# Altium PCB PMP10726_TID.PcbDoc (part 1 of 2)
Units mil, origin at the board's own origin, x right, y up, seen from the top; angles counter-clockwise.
Board outline 1200 x 2800 mil, 4 copper layers (Top Layer, Inner Layer 1, Inner Layer 2, Bottom Layer), stack 60.2 mil thick; 86 components, 43 nets, 209 pads, 170 vias.
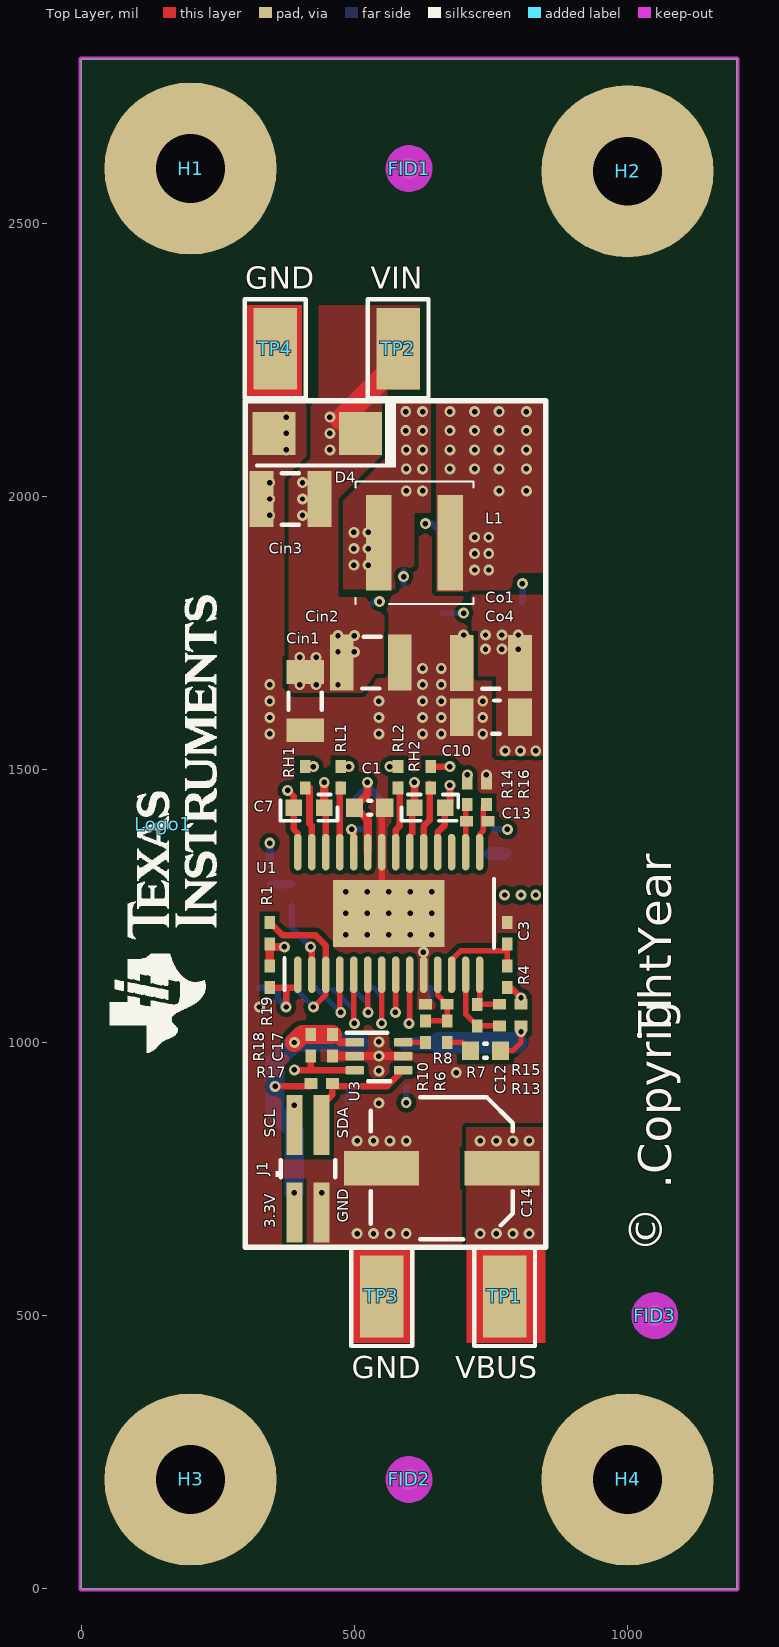
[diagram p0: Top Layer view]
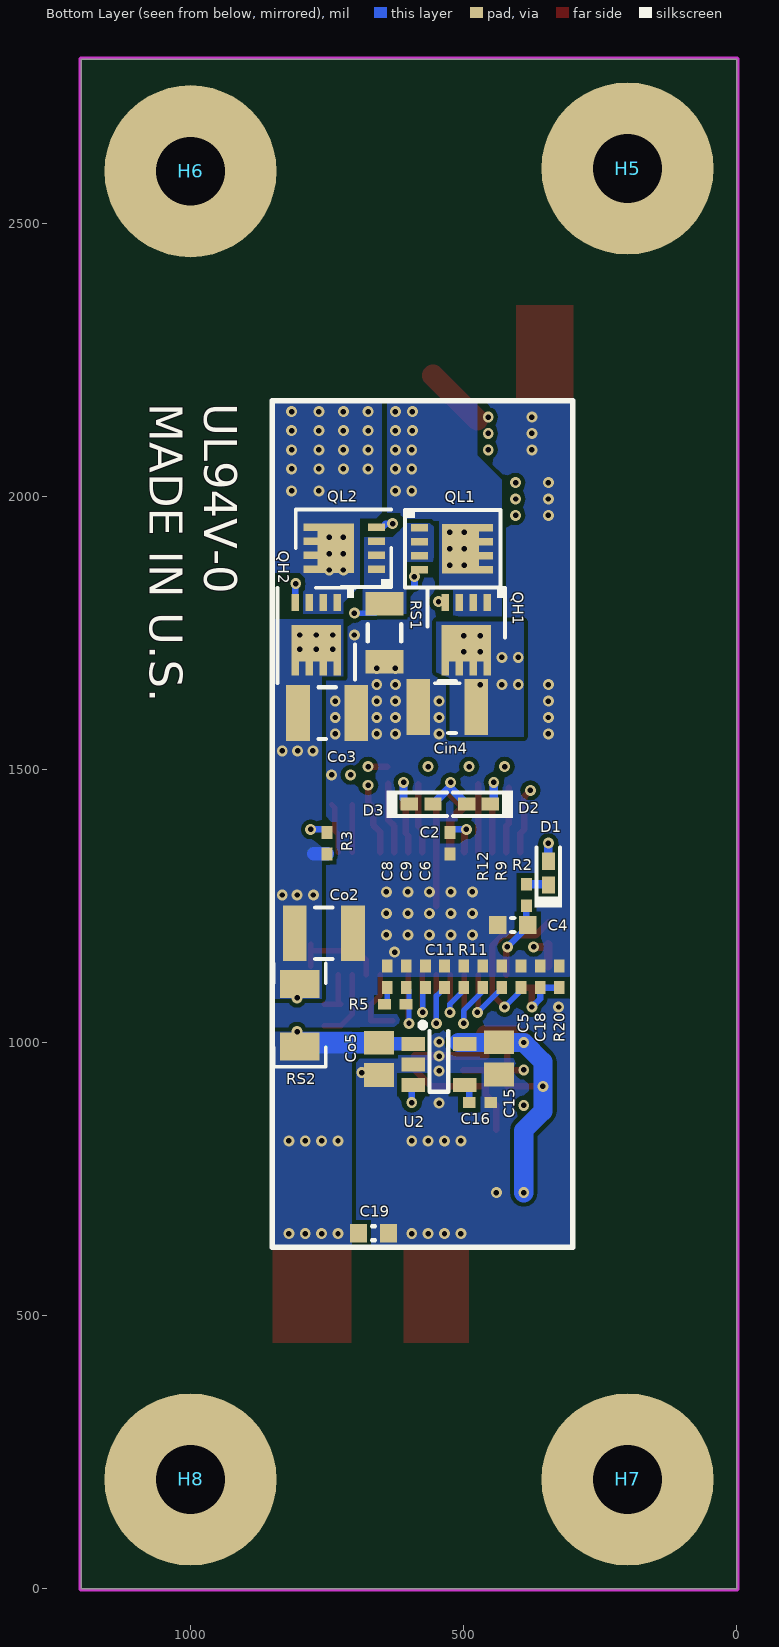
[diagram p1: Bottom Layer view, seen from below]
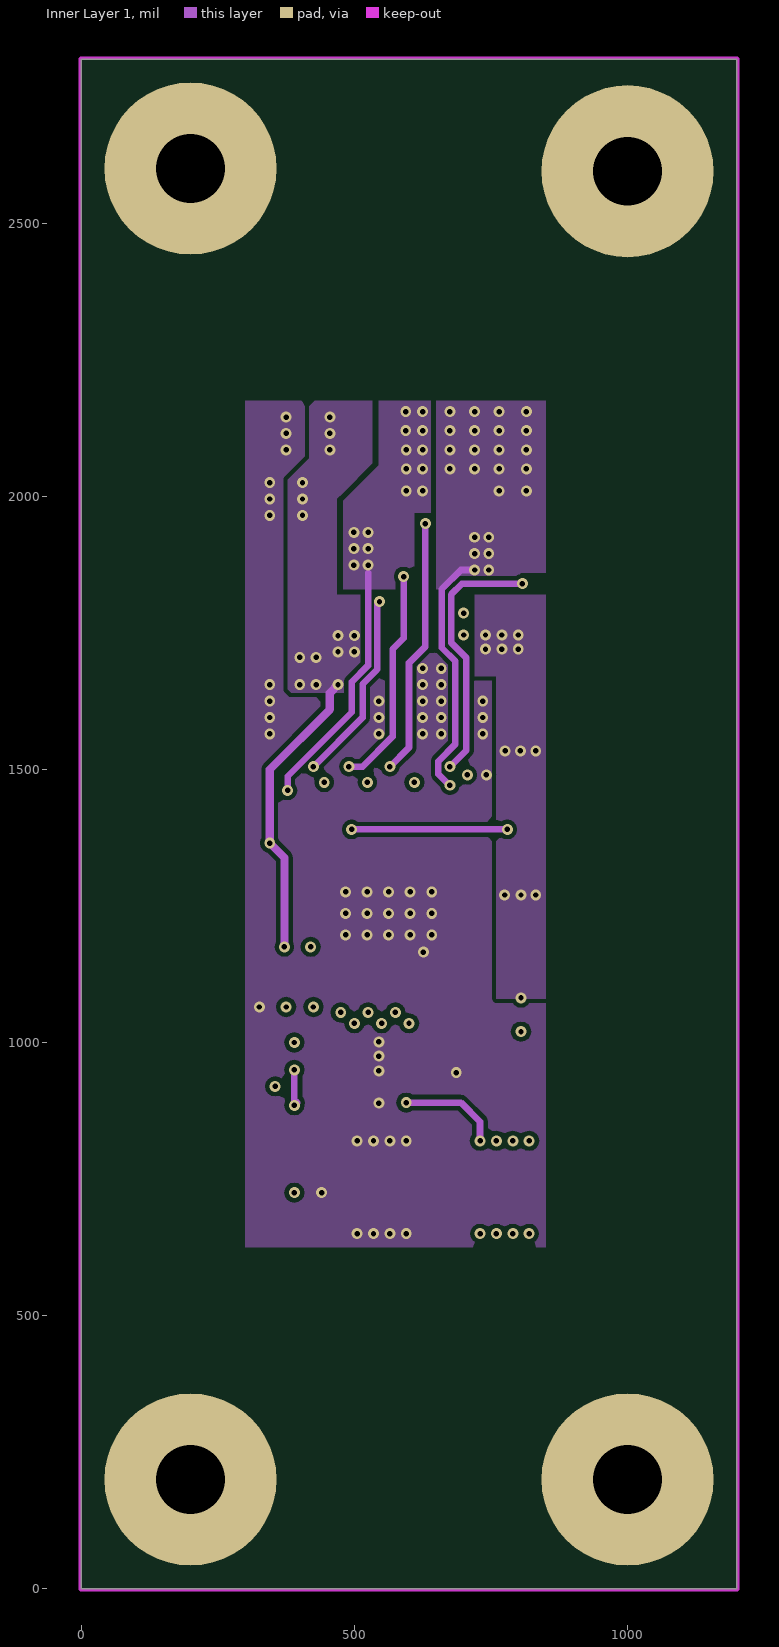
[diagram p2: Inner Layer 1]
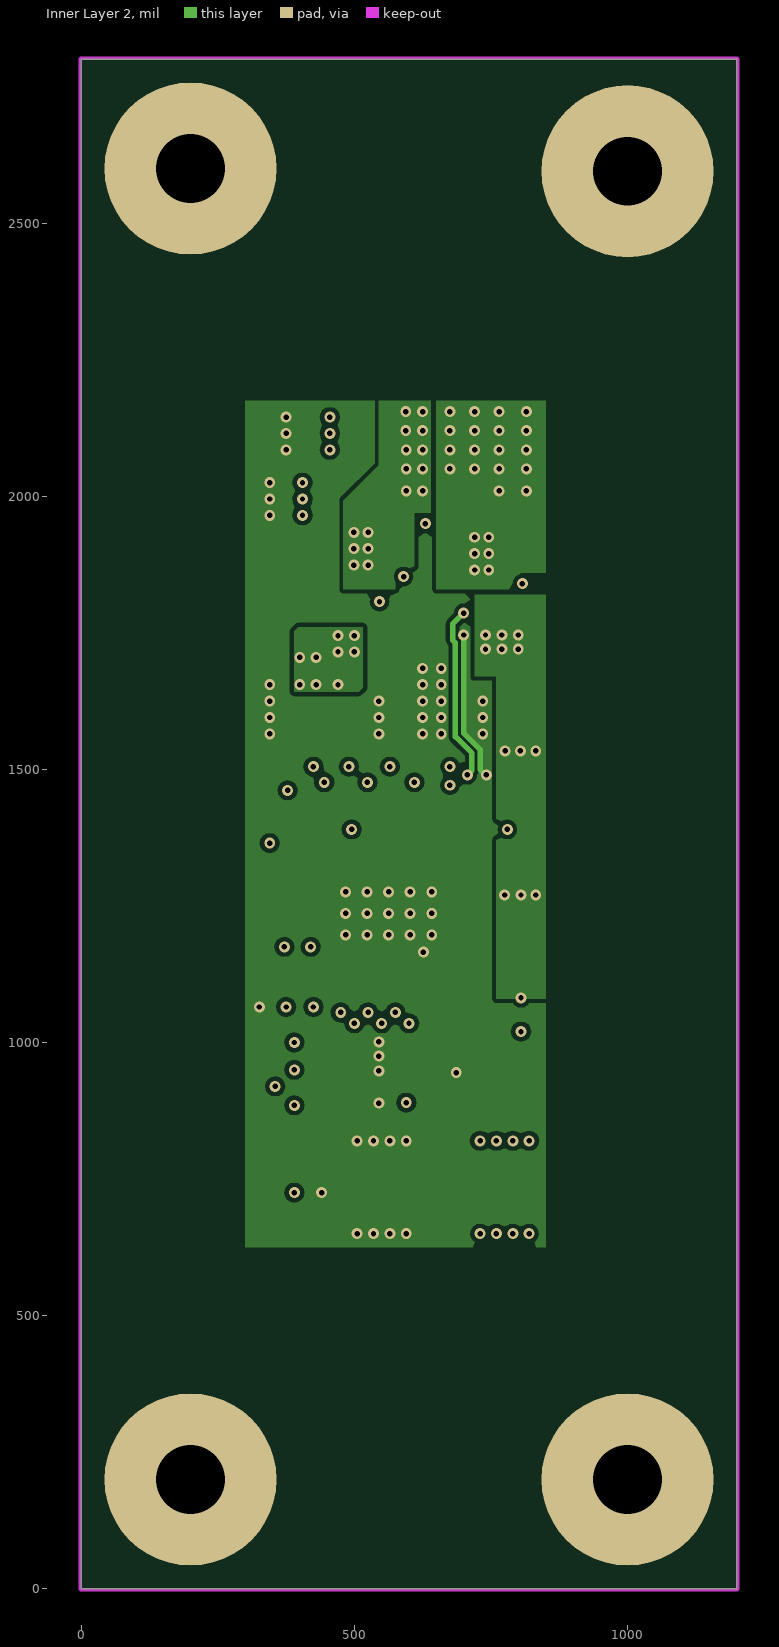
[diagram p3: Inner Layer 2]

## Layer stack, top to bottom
Top Solder: solder mask 0.5, Solder Resist, Dk 3.5
Top Layer: signal copper 2.8
Dielectric 1: prepreg 9.1, FR-4, Dk 4.2
Inner Layer 1: signal copper 2.8
Dielectric 2: core 30.8, FR-4, Dk 4.2
Inner Layer 2: signal copper 2.8
Dielectric 3: prepreg 9.1, FR-4, Dk 4.2
Bottom Layer: signal copper 2.8
Bottom Solder: solder mask 0.5, Solder Resist, Dk 3.5

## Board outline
0,0 1200,0 1200,2800 0,2800

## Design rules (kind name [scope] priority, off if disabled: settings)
AcuteAngle [All] p1: minimum=4.50000000000000E+0001 checktracksonly=FALSE
AssemblyTestPointUsage [All] p1: valid=2
Clearance "Clearance_POLY to NPTH" [HasFootprint('CONN_JPD1135-509') vs InPolygon] p1: gap=10
Clearance Clearance_Keepouts [((IsTrack Or IsArc) And Not InPoly) And IsFree and IsKeepOut vs ((IsTrack Or IsArc) And Not InPoly) And IsFree and IsKeepOut] p2: gap=0
Clearance Clearance_BoardEdge_MountingHoles [OnCopper and InComponentClass('Mounting Holes') vs IsKeepOut] p3: gap=40
Clearance Clearance_BoardEdge_Poly [OnCopper and InPoly vs IsKeepOut] p4: gap=25
Clearance Clearance_BoardEdge [OnCopper and Not InComponentClass('Logo') and not InComponentClass('FiducialMark') and not InRegion(1000,500,4000,800) and Not IsKeepout vs IsKeepOut] p5: gap=20
Clearance Clearance_Poly [InPolygon] p6: gap=8
Clearance [All] p7: gap=5
ComponentClearance ComponentClearance_MountingHoles_FiducialMarks [InComponentClass('Mounting Holes') vs InComponentClass('FiducialMark')] p1: gap=20 collisioncheckmode=3 verticalgap=10 showdistances=FALSE
ComponentClearance ComponentClearance_Shunt [InComponentClass('Header') vs InComponentClass('Shunt')] p2: gap=0 collisioncheckmode=3 verticalgap=0 showdistances=FALSE
ComponentClearance ComponentClearance_Logo [InComponentClass('Logo')] p3: gap=50 collisioncheckmode=3 verticalgap=10 showdistances=FALSE
ComponentClearance ComponentClearance_ScrewToNut [(HasFootprint('NY PMS 440 0025 PH')) vs (HasFootprint('Keystone_1902C'))] p4: gap=5 collisioncheckmode=3 verticalgap=10 showdistances=FALSE
ComponentClearance ComponentClearance_MountingHoles [InComponentClass('Mounting Holes')] p5: gap=50 collisioncheckmode=3 verticalgap=100000 showdistances=FALSE
ComponentClearance ComponentClearance_SmallPassives [HasFootprint('0201*') or HasFootprint('0402*') or HasFootprint('0508') or HasFootprint('0603*') or HasFootprint('0612') or HasFootprint('0805*') or HasFootprint('0815*') or HasFootprint('0830*') or HasFootprint('1206*') or HasFootprint('1210*') or HasFootprint('1808*') or HasFootprint('1812*') or HasFootprint('1825*') or HasFootprint('2010*') or HasFootprint('2220*') or HasFootprint('2225*') or HasFootprint('2512*') or HasFootprint('2728*') or HasFootprint('3518*') vs HasFootprint('0201*') or HasFootprint('0402*') or HasFootprint('0508') or HasFootprint('0603*') or HasFootprint('0612') or HasFootprint('0805*') or HasFootprint('0815*') or HasFootprint('0830*') or HasFootprint('1206*') or HasFootprint('1210*') or HasFootprint('1808*') or HasFootprint('1812*') or HasFootprint('1825*') or HasFootprint('2010*') or HasFootprint('2220*') or HasFootprint('2225*') or HasFootprint('2512*') or HasFootprint('2728*') or HasFootprint('3518*')] p6: gap=10 collisioncheckmode=3 verticalgap=10 showdistances=FALSE
ComponentClearance ComponentClearance_THtoSMT [IsThruComponent vs IsSMTComponent] p7: gap=20 collisioncheckmode=3 verticalgap=30 showdistances=FALSE
ComponentClearance ComponentClearance_THtoTH [IsThruComponent vs IsThruComponent] p8: gap=50 collisioncheckmode=3 verticalgap=30 showdistances=FALSE
ComponentClearance [All] p9: gap=9.9 collisioncheckmode=3 verticalgap=10 showdistances=FALSE
DiffPairsRouting [All] p1: maxlimit=100 minlimit=6 mostfreqgap=6 toplayer_minwidth=4 toplayer_maxwidth=15 toplayer_prefwidth=5 midlayer1_minwidth=4 midlayer1_maxwidth=15 midlayer1_prefwidth=5 midlayer2_minwidth=4 midlayer2_maxwidth=15 midlayer2_prefwidth=5 bottomlayer_minwidth=4 bottomlayer_maxwidth=15 bottomlayer_prefwidth=5 maxuncoupledlength=1000
FabricationTestPointUsage TestPointUsage [All] p1: valid=2 allowmultiple=FALSE
FabricationTestpoint Testpoint [All] p1: side=3 testpointundercomponent=TRUE minsize=40 maxsize=100 preferedsize=60 minholesize=0 maxholesize=40 preferedholesize=32 testpointgrid=1 allowsidetop=TRUE allowsidebottom=TRUE usegrid=TRUE gridtolerance=0.01
FanoutControl Fanout_LCC [IsLCC] p1: bgadir=Out bgaviamode=Centered fanoutstyle=Auto fanoutdirection=Alternating viagrid=1 // Fanout_LCC (Default Rule)
FanoutControl Fanout_BGA [IsBGA] p2: bgadir=Out bgaviamode=Centered fanoutstyle=Auto fanoutdirection=Alternating viagrid=1 // Fanout_BGA (Default Rule)
FanoutControl Fanout_Default [All] p4: bgadir=Out bgaviamode=Centered fanoutstyle=Auto fanoutdirection=Alternating viagrid=1 // Fanout_Default (Default Rule)
FanoutControl Fanout_Small [(CompPinCount < 5)] p5: bgadir=Out bgaviamode=Centered fanoutstyle=Auto fanoutdirection=OutThenIn viagrid=1 // Fanout_Small (Default Rule)
HoleSize [All] p1: absolutevalues=TRUE maxlimit=251 minlimit=10 maxpercent=80.000 minpercent=20.000
HoleToHoleClearance "HoleToHoleClearance_USB-C Connector" [HasFootprint('Lintes_20-0000016-01') vs HasFootprint('Lintes_20-0000016-01')] p1: gap=0 allowstackedmicrovias=TRUE
HoleToHoleClearance [All] p2: gap=10 allowstackedmicrovias=TRUE
MinimumAnnularRing MinimumAnnularRing_ThermalPadVias [IsVia and InAnyComponent] p1: minimumring=5
MinimumAnnularRing [All] p2: minimumring=5
MinimumSolderMaskSliver "MinimumSolderMaskSliver_USB-C Connector" [HasFootprint('Lintes_20-0000016-01')] p1: minsoldermaskwidth=3.6
MinimumSolderMaskSliver MinimumSolderMaskSliver_FemtoFET [HasFootprint('YJC0003A') vs HasFootprint('YJC0003A')] p2: minsoldermaskwidth=3.54
MinimumSolderMaskSliver MinimumSolderMaskSliver_LM53600 [HasFootprint('DSX0010A') vs HasFootprint('DSX0010A')] p3: minsoldermaskwidth=0
MinimumSolderMaskSliver MinimumSolderMaskSliver_TPS65982 [HasFootprint('ZQZ0096A_Oval')] p4: minsoldermaskwidth=3.6
MinimumSolderMaskSliver MinimumSolderMaskSliver_Logo [InComponentClass('Logo') vs InComponentClass('Logo')] p5: minsoldermaskwidth=0.7
MinimumSolderMaskSliver [All] p6: minsoldermaskwidth=2
ParallelSegment [All] p1: limit=500 gap=4
PlaneClearance [All] p1: clearance=10
PlaneConnect [All] p1: planeconnectstyle=Direct reliefexpansion=10 reliefentries=4 reliefconductorwidth=10 reliefairgap=10
PolygonConnect [All] p1: connectstyle=Direct reliefconductorwidth=10 reliefentries=4 polygonreliefangle="90 Angle" airgapwidth=10
RoutingVias ThermalPadVias [IsVia and InAnyComponent] p1: holewidth=7.87 width=19.68 viastyle="Through Hole" minholewidth=7.87 minwidth=16 maxholewidth=12.99 maxwidth=23.62
RoutingVias [All] p2: holewidth=16 width=34 viastyle="Through Hole" minholewidth=7.87 minwidth=16 maxholewidth=40 maxwidth=65
SilkToBoardRegionClearance [Not ((IsComment or IsDesignator) And (Hide <> 'False')) and not InRegion(1000,500,4000,800)] p1:
SilkToSilkClearance SilkToSilkClearance_Pb-FreeLogo [(HasFootprint('Pb-Free_Overlay_Medium') OR HasFootprint('Pb-Free_Overlay_Small')) vs (HasFootprint('Pb-Free_Overlay_Medium') OR HasFootprint('Pb-Free_Overlay_Small'))] p1: silktosilkclearance=0
SilkToSilkClearance [All] p2: silktosilkclearance=3
SilkToSolderMaskClearance "Silk to Solder Mask Opening" [All] p1: minsilkscreentomaskgap=1 clearancetoexposedcopper=FALSE
SolderMaskExpansion [All] p1: expansion=1.97
Width [All] p1: maxlimit=100 minlimit=5 preferedwidth=8
13 further rules are at their usual default settings.

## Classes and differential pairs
component class PMP10726B_Power: C1 C2 C3 C4 C5 C6 C7 C8 C9 C10 C11 C12 C13 C14 C15 C16 C17 C18 C19 C? Cin1 Cin2 Cin3 Cin4 Co1 Co2 Co3 Co4 Co5 D1 D2 D3 D4 L1 QH1 QH2 QL1 QL2 R1 R2 R3 R4 R5 R6 R7 R8 R9 R10 R11 R12 R13 R14 R15 R16 R17 R18 R19 R20 RH1 RH2 RL1 RL2 RS1 RS2 TP1 TP2 TP3 TP4 U1 U2 U3
component class AssemblyNote: ZZ1 ZZ2 ZZ3
component class FiducialMark: FID1 FID2 FID3
component class PMP10726B_Misc: FID1 FID2 FID3 H1 H2 H3 H4 H5 H6 H7 H8 Logo1 ZZ1 ZZ2 ZZ3
component class Logo: Logo1
component class "Mounting Holes": H1 H2 H3 H4

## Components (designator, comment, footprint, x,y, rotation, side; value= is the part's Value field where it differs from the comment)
C1 "GRM188R71E105KA12D" 0603l 528,1430 r0 top
C2 "C1005X7R1C224K050BC" 0402L 525,1365 r90 bottom
C3 "GRM1535C1H101JDD5D" 0402L 780,1200 r270 top
C4 "C1608X7R1H224K080AB" 0603L 410,1215 r180 bottom
C5 "GRM1535C1H101JDD5D" 0402L 395,1120 r270 bottom
C6 "C1005X7R1H473K050BB" 0402L 570,1120 r270 bottom
C7 "GCM188R71H104KA57D" 0603_HV 417,1430 r180 top
C8 "GCM155R71H223KA55D" 0402l 640,1120 r270 bottom
C9 "GRM1555C1H221JA01D" 0402l 605,1120 r270 bottom
C10 "GCM188R71H104KA57D" 0603_HV 638,1430 r0 top
C11 "GRM1555C1H680JA01D" 0402l 535,1120 r90 bottom
C12 "GRM1535C1H101JDD5D" 0402l 725,1050 r90 top
C13 "GRM1555C1H221JA01D" 0402l 725,1405 r0 top
C14 "UUD1C101MCL1GS" SM_RADIAL_6.3AMM 660,770 r180 top
C15 "GRM21BR71C475KA73L" 0805L 435,971 r90 bottom
C16 "GCM155R71H103KA55D" 0402L 470,890 r0 bottom
C17 "C1005X7R1C224K050BC" 0402L 460,995 r90 top
C18 "GRM1535C1H101JDD5D" 0402L 359.94,1120 r90 bottom
C19 "GRM188R71E105KA12D" 0603L 665,651 r0 bottom
Cin1 "GRM31CR71H475KA12L" 1206L 410,1625 r270 top
Cin2 "GRM32ER71H106KA12L" 1210L 530,1695.31 r0 top
Cin3 "GRM32ER71H106KA12L" 1210L 383,1995 r180 top
Cin4 "GRM32ER71H106KA12L" 1210L 530,1614 r0 bottom
Co1 "GRM32ER71E226KE15L" 1210L 750,1695 r180 top
Co2 "GRM32ER71E226KE15L" 1210L 755.73,1200 r180 bottom
Co3 "GRM32ER71E226KE15L" 1210L 750,1603 r180 bottom
Co4 "C3216X7R1E106M160AE" 1206L 750,1595.31 r180 top
Co5 "EMK212BB7106MG-T" 0805L 655,970 r270 bottom
D1 "BAS 52-02V H6327" SOD-523 345,1310 r90 bottom
D2 "BAS516,115" SOD-523 472.82,1436.3 r0 bottom
D3 "BAS516,115" SOD-523 577.82,1436.3 r180 bottom
D4 "SMAJ30CA" SMA 432,2115 r180 top
FID1 "Fiducial" Fiducial10-20 600,2600 r0 top
FID2 "Fiducial" Fiducial10-20 600,200 r0 top
FID3 "Fiducial" Fiducial10-20 1050,500 r0 top
H1 "NY PMS 440 0025 PH" "NY PMS 440 0025 PH" 200,2600 r0 top locked
H2 "NY PMS 440 0025 PH" "NY PMS 440 0025 PH" 1000,2595 r0 top locked
H3 "NY PMS 440 0025 PH" "NY PMS 440 0025 PH" 200,200 r0 top locked
H4 "NY PMS 440 0025 PH" "NY PMS 440 0025 PH" 1000,200 r0 top locked
H5 "1902C" Keystone_1902C 200,2600 r180 bottom locked
H6 "1902C" Keystone_1902C 1000,2595 r180 bottom locked
H7 "1902C" Keystone_1902C 200,200 r180 bottom locked
H8 "1902C" Keystone_1902C 1000,200 r180 bottom locked
J1 "FTSH-102-01-F-DV" Samtec_FTSH-102-01-x-DV 415,769 r90 top
L1 "XAL5050-562MEB" XAL5050 610,1915 r0 top
Logo1 "Texas Instruments" TI_Stacked_Overlay_Small 150,1400 r90 top
QH1 "BSZ025N04LSATMA1" PG-TSDSON-8 495,1745 r270 bottom
QH2 "BSZ025N04LSATMA1" PG-TSDSON-8 770,1745 r270 bottom
QL1 "BSZ025N04LSATMA1" PG-TSDSON-8 520,1904 r180 bottom
QL2 "BSZ025N04LSATMA1" PG-TSDSON-8 720,1905 r0 bottom
R1 "CRCW040210R0JNED" 0402l 345,1200 r270 top
R2 "CRCW040210R0JNED" 0402l 385,1270 r90 bottom
R3 "CRCW040210R0JNED" 0402l 750,1365 r270 bottom
R4 "CRCW040210R0JNED" 0402L 780,1120 r270 top
R5 "CRCW04023K32FKED" 0402l 625,1070 r180 bottom
R6 "CRCW040249K9FKED" 0402L 670,1020 r90 top
R7 "CRCW060324R9FKEA" 0603L 740,985 r0 top
R8 "CRCW0402115KFKED" 0402L 650,1070 r180 top
R9 "CRCW0402100KFKED" 0402l 430,1120 r90 bottom
R10 "CRCW04023K57FKED" 0402L 630,1020 r270 top
R11 "CRCW040264K9FKED" 0402l 500,1120 r90 bottom
R12 "CRCW04020000Z0ED" 0402l 465,1120 r90 bottom
R13 "CRCW04020000Z0ED" 0402L 785,1030 r180 top
R14 "CRCW0402100RFKED" 0402l 706.81,1455.35 r90 top
R15 "CRCW04020000Z0ED" 0402L 785,1070 r180 top
R16 "CRCW0402100RFKED" 0402l 741.81,1455.35 r90 top
R17 "CRCW04023K32FKED" 0402L 440,925 r180 top
R18 "CRCW04023K32FKED" 0402L 420,995 r90 top
R19 "CRCW0402200KFKED" 0402L 345,1120 r270 top
R20 "CRCW040249K9FKED" 0402L 324.94,1120 r90 bottom
RH1 "CRCW04020000Z0ED" 0402L 410,1485.35 r90 top
RH2 "CRCW04020000Z0ED" 0402L 640,1485.35 r270 top
RL1 "CRCW04020000Z0ED" 0402L 475,1485.35 r90 top
RL2 "CRCW04020000Z0ED" 0402L 580,1485.35 r270 top
RS1 "WSLP1206R0100FEA" 1206L 645,1750 r90 bottom
RS2 "WSLP1206R0100FEA" 1206 800,1050 r270 bottom
TP1 "VBUS" Keystone_5019 775,535 r90 top
TP2 "VIN" Keystone_5019 580,2270 r90 top
TP3 "GND" Keystone_5019 550,535 r270 top
TP4 "GND" Keystone_5019 355,2270 r90 top
U1 "LM5175PWPR" PWP0028F_N 562.82,1236.3 r90 top
U2 "LP2985AIM5-3.3/NOPB" MF05A_N 545,960 r180 bottom
U3 "TPL0401A-10DCKR" DCK0006A_N 545,975 r0 top
ZZ1 "These assemblies are ESD sensitive, ESD precautions shall be observed." AssemblyNote -11,3159 r0 top
ZZ2 "These assemblies must be clean and free from flux and all contaminants. Use of no clean flux is not acceptable." AssemblyNote -11,3079 r0 top
ZZ3 "These assemblies must comply with workmanship standards IPC-A-610 Class 2, unless otherwise specified." AssemblyNote -11,2999 r0 top

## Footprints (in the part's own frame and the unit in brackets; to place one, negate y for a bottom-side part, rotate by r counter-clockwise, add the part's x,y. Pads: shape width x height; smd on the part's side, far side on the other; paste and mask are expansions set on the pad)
0402L [mm] "0402 from SM-752 data"
  rect 0.6x0.5 smd: 1(-0.5,0) 2(0.5,0)
  body extent -0.55,-0.3 0.55,0.3, height 0.6
0402l [mm] "0402 from SM-752 data"
  rect 0.6x0.5 smd: 1(-0.5,0) 2(0.5,0)
  body extent -0.55,-0.3 0.55,0.3, height 0.6
0603_HV [mil] "Ernesto recommended land pattern.  26 mil between pads."
  rect 30x30 smd: 1(-28,0) 2(28,0)
  silkscreen extent -52,-24 52,24, body extent -34,-19 34,19, height 33
0603l [mm] "0603 from SM-752 data"
  rect 0.8x0.85 smd: 1(-0.7,0) 2(0.7,0)
  silkscreen extent -0.07,-0.33 0.07,0.33, body extent -0.87,-0.47 0.87,0.47, height 0.85
0603L [mm] "0603 from SM-752 data"
  rect 0.8x0.85 smd: 1(-0.7,0) 2(0.7,0)
  silkscreen extent -0.07,-0.33 0.07,0.33, body extent -0.87,-0.47 0.87,0.47, height 0.85
0805L [mm] "0805 from SM-752 data"
  rect 1.1x1.4 smd: 1(-0.75,0) 2(0.75,0)
  body extent -1.1,-0.72 1.1,0.72, height 1.45
1206 [mm] "1206 from SM-752 data"
  rect 1.3x1.85 smd: 1(-1.45,0) 2(1.45,0)
  silkscreen extent -2.4,-1.21 2.4,1.21, body extent -1.7,-0.9 1.7,0.9, height 1.35
1206L [mm] "1206 from SM-752 data"
  rect 1.1x1.75 smd: 1(-1.35,0) 2(1.35,0)
  silkscreen extent -0.4,-0.77 0.4,0.77, body extent -1.7,-0.9 1.7,0.9, height 1.35
1210L [mm] "1210 from SM-752 data"
  rect 1.1x2.6 smd: 1(-1.35,0) 2(1.35,0)
  silkscreen extent -0.4,-1.2 0.47,1.21, body extent -1.7,-1.35 1.7,1.35, height 1.35
AssemblyNote [mil] "Assembly Note"
DCK0006A_N [mm] "SOT23, 6-Leads, Body 2x1.3mm, Pitch 0.65mm, Lead Span 2.1mm, IPC Medium Density"
  rrect25% 0.85x0.4 smd: 1(-1.125,0.65) 2(-1.125,0) 3(-1.125,-0.65) 4(1.125,-0.65) 5(1.125,0) 6(1.125,0.65)
  silkscreen extent -1.5,-1.17 0.53,1.09, body extent -1.14,-1 1.14,1, height 0.95
Fiducial10-20 [mm]
  round 1 smd mask+0.5: 1(0,0)
  Top Layer keep-out circle w1.178: c0,0 r0.5
Keystone_1902C [mil] "Hex Standoff, 4-40 threaded, nylon"
  body extent -145,-126 146,126, height 501
Keystone_5019 [mm] "Test Point, Miniature, SMT"
  rect 3.8x2.03 smd: 1(0,0)
  silkscreen extent -2.31,-1.42 2.31,1.42, body extent -1.9,-1.02 1.9,1.02, height 2.29
MF05A_N [mm] "SOT23, 5-Leads, Body 2.9x1.6mm, Pitch 0.95mm, Lead Span 2.8mm, IPC Medium Density"
  rect 1.1x0.65 smd: 1(-1.2,0.95) 2(-1.2,0) 3(-1.2,-0.95) 4(1.2,-0.95) 5(1.2,0.95)
  silkscreen extent -0.89,-1.27 0.43,1.95, body extent -0.9,-1.55 0.9,1.55, height 1.19
"NY PMS 440 0025 PH" [mm] "4-40 nylon screw and mounting hole"
  round 8 hole 3.2: 1(0,0)
  body extent -3.3,-3.3 3.3,3.3, height 2.69
PG-TSDSON-8 [mm] "Infineon recommended land pattern"
  rect 0.8x0.34 smd: 1(-1.538,0.975) 2(-1.538,0.325) 3(-1.538,-0.325) 4(-1.538,-0.975)
  rect 0.65x0.34 smd: 5(1.538,-0.975) 6(1.538,-0.325) 7(1.538,0.325) 8(1.538,0.975)
  rect 1.71x2.29 smd: 9(0.358,0)
  silkscreen extent -2.22,-1.8 2.22,1.8, body extent -1.7,-1.7 1.7,1.7, height 1.1
PWP0028F_N [mm] "TSOP, 28-Leads, Body 9.7x4.4mm, Pitch 0.65mm, Exposed Pad, IPC Medium Density"
  oval 1.7x0.35 smd: 1(-2.85,4.225) 2(-2.85,3.575) 3(-2.85,2.925) 4(-2.85,2.275) 5(-2.85,1.625) 6(-2.85,0.975) 7(-2.85,0.325) 8(-2.85,-0.325) 9(-2.85,-0.975) 10(-2.85,-1.625) 11(-2.85,-2.275) 12(-2.85,-2.925) 13(-2.85,-3.575) 14(-2.85,-4.225) 15(2.85,-4.225) 16(2.85,-3.575) 17(2.85,-2.925) 18(2.85,-2.275) 19(2.85,-1.625) 20(2.85,-0.975) 21(2.85,-0.325) 22(2.85,0.325) 23(2.85,0.975) 24(2.85,1.625) 25(2.85,2.275) 26(2.85,2.925) 27(2.85,3.575) 28(2.85,4.225)
  rect 3.1x5.18 smd: 29(0,0)
  silkscreen extent -3.56,-4.9 1.6,4.85, body extent -3.21,-4.85 3.21,4.85, height 0.98
Samtec_FTSH-102-01-x-DV [mm] "Header, 1.27mm, 2x2, SMT"
  rect 2.79x0.74 smd: 1(-2.035,0.635) 2(2.035,0.635) 3(-2.035,-0.635) 4(2.035,-0.635)
  silkscreen extent -0.4,-1.27 0.4,1.5, body extent -2.92,-1.27 2.92,1.27, height 5.97
SM_RADIAL_6.3AMM [mm] "Nichicon 6.3x5.8"
  rect 3.5x1.6 smd: 1(-2.8,0) 2(2.8,0)
  silkscreen extent -3.3,-3.29 3.3,3.31, body extent -3.5,-3.3 3.5,3.3, height 6.11
SMA [mm] "Molded Diode, 2-Leads, Body 4.3x2.6mm, IPC Medium Density, based on OnSemi component dimensions and land pattern"
  rect 2x2 smd: 1(-2,0) 2(2,0)
  silkscreen extent -3.66,-1.57 2.79,1.57, body extent -2.6,-1.3 2.6,1.3, height 2.42
SOD-523 [mm] "NXP Semiconductor recommended land pattern, nominal STEP model"
  rect 0.8x0.6 smd paste-0.05: 1(-0.55,0) 2(0.55,0)
  silkscreen extent -1.6,-0.64 1.2,0.63, body extent -0.8,-0.4 0.8,0.4, height 0.72
TI_Stacked_Overlay_Small [mil]
  silkscreen extent -418,-98 418,98
XAL5050 [mm] "CoilCraft XAL5050 5.28 x 5.48 x 5.1 mm"
  rect 1.18x4.44 smd: 1(-1.655,0) 2(1.655,0)
  silkscreen extent -2.75,-2.85 2.75,2.85, body extent -2.74,-2.84 2.74,2.84, height 5.1

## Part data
C1 C19: "CAP, CERM, 1 µF, 25 V, +/- 10%, X7R, 0603"
C2 C17: "CAP, CERM, 0.22 µF, 16 V, +/- 10%, X7R, 0402"
C3 C5 C12 C18: "CAP, CERM, 100 pF, 50 V, +/- 5%, C0G/NP0, 0402"
C4: "CAP, CERM, 0.22uF, 50V, +/-10%, X7R, 0603"
C6: "CAP, CERM, 0.047 µF, 50 V, +/- 10%, X7R, 0402"
C7 C10: "CAP, CERM, 0.1 µF, 50 V, +/- 10%, X7R, 0603"
C8: "CAP, CERM, 0.022 µF, 50 V, +/- 10%, C0G/NP0, 0402"
C9 C13: "CAP, CERM, 220 pF, 50 V, +/- 5%, C0G/NP0, 0402"
C11: "CAP, CERM, 68 pF, 50 V, +/- 5%, C0G/NP0, 0402"
C14: "CAP, AL, 100 µF, 16 V, +/- 20%, 0.44 ohm, SMD"
C15: "CAP, CERM, 4.7 µF, 16 V, +/- 10%, X7R, 0805"
C16: "CAP, CERM, 0.01 µF, 50 V, +/- 10%, C0G/NP0, 0402"
Cin1: "CAP, CERM, 4.7 µF, 50 V, +/- 10%, X7R, 1206"
Cin2 Cin3 Cin4: "CAP, CERM, 10 µF, 50 V, +/- 10%, X7R, 1210"
Co1 Co2 Co3: "CAP, CERM, 22 µF, 25 V, +/- 10%, X7R, 1210"
Co4: "CAP, CERM, 10 µF, 25 V, +/- 20%, X7R, 1206_190"
Co5: "CAP, CERM, 10 µF, 16 V, +/- 20%, X7R, 0805"
D1: "Diode, Schottky, 45 V, 0.75 A, SOD-523"
D2 D3: "Diode, Switching, 100V, 0.25A, SOD-523"
D4: "Diode, TVS, Bi, 30 V, 400 W, SMA"
FID1 FID2 FID3: "Fiducial mark.  There is nothing to buy or mount."
H1 H2 H3 H4: "Machine Screw, Round, #4-40 x 1/4, Nylon, Philips panhead"
H5 H6 H7 H8: "Standoff, Hex, 0.5\"L #4-40 Nylon"
J1: "Header, 1.27mm, 2x2, Gold, SMT"
L1: "Inductor, Shielded, Composite, 5.6 µH, 6.3 A, 0.03 ohm, SMD"
Logo1: library part TI_Logo, "Texas Instrument Corporate Signature"
QH1 QH2 QL1 QL2: library part "BSZ040N04LS G", "MOSFET, N-CH, 40 V, 40 A, PG-TSDSON-8"
R1 R2 R3 R4: "RES, 10, 5%, 0.063 W, 0402"
R5 R17 R18: "RES, 3.32 k, 1%, 0.063 W, 0402"
R6 R20: "RES, 49.9 k, 1%, 0.063 W, 0402"
R7: "RES, 24.9, 1%, 0.1 W, 0603"
R8: "RES, 115 k, 1%, 0.063 W, 0402"
R9: "RES, 100 k, 1%, 0.063 W, 0402"
R10: "RES, 3.57 k, 1%, 0.063 W, 0402"
R11: "RES, 64.9 k, 1%, 0.063 W, 0402"
R12 R13 R15 RH1 RH2 RL1 RL2: "RES, 0, 5%, 0.063 W, 0402"
R14 R16: "RES, 100, 1%, 0.063 W, 0402"
R19: "RES, 200 k, 1%, 0.063 W, 0402"
RS1 RS2: "RES, 0.01, 1%, 1 W, 1206"
TP1 TP2 TP3 TP4: library part 5019, "Test Point, Miniature, SMT"
U1: "42V Wide VIN 4-Switch Synchronous Buck-Boost Controller, PWP0028F"
U2: "Micropower 150 mA Low-Noise Ultra Low-Dropout Regulator, 5-pin SOT-23, Pb-Free"
U3: "128 TAPS Single Channel Digital Potentiometer with I2C Interface, DCK0006A"
ZZ1 ZZ2 ZZ3: library part AssemblyNote

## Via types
v1: diameter 20, hole 10, Top Layer to Bottom Layer, 93 vias
v2: diameter 20, hole 10, Top Layer to Bottom Layer, tented both sides, 77 vias

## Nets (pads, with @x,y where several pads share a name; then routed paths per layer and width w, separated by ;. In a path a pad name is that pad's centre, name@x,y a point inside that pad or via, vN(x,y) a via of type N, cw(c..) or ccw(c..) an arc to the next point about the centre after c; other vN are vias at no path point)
BIAS: C2.2 R3.1 U1.24 | length 379.6
  Top Layer w12: v1(495,1390) 498.47,1386.53 U1.24@498.47,1348.87 ; U1.24@498.84,1348.5 U1.24@498.47,1348.87 ; U1.24@500,1350.4 U1.24@498.47,1348.87
  Inner Layer 1 w12: v1(495,1390) v1(780,1390)
  Bottom Layer w12: v1(495,1390) C2.2@519.69,1390 ; R3.1@755.32,1390 v1(780,1390)
BOOT1: C7.1 D2.1 U1.26 | length 162.6
  Top Layer w12: C7.1@444.82,1431.3 445.56,1430.56 447.66,1428.46 U1.26@447.66,1348.5
  Top Layer w15: C7.1@444.82,1431.3 v1(444.82,1476.3)
  Bottom Layer w15: D2.1@444.82,1442.65 v1(444.82,1476.3)
BOOT2: C10.1 D3.1 U1.20 | length 155.4
  Top Layer w12: U1.20@601.2,1348.5 601.2,1378.68 605.82,1383.3 C10.1@605.82,1427.3
  Top Layer w15: C10.1@609.82,1431.3 v1(609.82,1476.3)
  Bottom Layer w15: D3.1@609.82,1446.65 v1(609.82,1476.3)
COMP: C9.2 R5.2 U1.9 | length 139.4
  Top Layer w10: 601.2,1045 U1.9@601.2,1124.09
  Bottom Layer w10: v1(600,1035) 600,1070 C9.2@600,1095.31
CS: C13.1 R14.1 U1.16 | length 87.2
  Top Layer w10: U1.16@703.56,1348.5 703.56,1405 R14.1@703.56,1435.67
CSG: C13.2 R16.1 U1.15 | length 92.4
  Top Layer w10: U1.15@729.15,1348.5 729.15,1380.77 736.22,1387.83 736.22,1405 736.22,1430.08 R16.1@741.81,1435.67
DITH: R12.1 U1.5 | length 165.7
  Top Layer w10: v1@498.84,1036.16 U1.5@498.84,1124.09
  Bottom Layer w10: R12.1@461.48,1096.8 500,1058.28 v1(500,1035)
EN_IC: C18.1 R19.2 R20.1 U1.1 | length 156.6
  Top Layer w12: R19.2@345,1100.31 375,1100.31 ; v1(375,1065) 375,1100.31 ; U1.1@389.69,1100.31 375,1100.31
  Bottom Layer w12: R20.1@324.94,1100.32 C18.1@359.94,1100.32 359.94,1080.06 v1(375,1065)
FB: R6.2 R8.1 R10.1 U1.11 | length 131.7
  Top Layer w10: R10.1@630,1039.68 R6.2@670,1039.69 670,1069.68 R8.1@669.68,1070 652.38,1087.3 U1.11@652.38,1124.09
GND: C1.2 C2.1 C3.1 C4.1 C5.1 C6.1 C8.1 C9.1 C11.2 C14.2 C15.1 C16.1 C17.1 C18.2 C19.1 Cin1.2 Cin2.2 Cin3.2 Cin4.2 Co1.2 Co2.2 Co3.2 Co4.2 Co5.2 D4.2 J1.3 R8.2 R9.2 R11.2 R12.2 R16.2 R20.2 RS1.1 TP3.1 TP4.1 U1.10 U1.22 U1.29 U2.2 U3.2 U3.5 | length 591.7
  Top Layer w12: U1.29@550.02,1249.09 U1.22@550.02,1348.5 C1.2@550.02,1437.94
  Top Layer w15: C17.1@460.32,975 U3.2@500.71,975 v2(545,975) U3.5@589.29,975
  Inner Layer 2 w10: v1(700,1746) 700,1566.21 730,1536.21 730,1500 v1@740.91,1489.09
  other v1: 440,725 545,889.13 686.5,945 326,1065 626.47,1165.3 484.08,1196.93 523.45,1196.93 562.82,1196.93 602.19,1196.93 641.56,1196.93 484.08,1236.3 523.45,1236.3 562.82,1236.3 602.19,1236.3 641.56,1236.3 484.08,1275.67 523.45,1275.67 562.82,1275.67 602.19,1275.67 641.56,1275.67 741.81,1490 345,1965 345,1995 345,2025 375,2085 375,2115 375,2145
  other v2: 505,650 535,650 565,650 595,650 505,820 535,820 565,820 595,820 545,948 545,1001 345,1565 545,1565 625,1565 659,1565 735,1565 345,1595 545,1595 625,1595 659,1595 735,1595 345,1625 545,1625 625,1625 659,1625 735,1625 345,1655 625,1655 659,1655 625,1685 659,1685
HDRV1_N: C7.2 L1.1 QH1.1 QH1.2 QH1.3 QL1.5 QL1.6 QL1.7 QL1.8 QL1.9 U1.28 | length 580.2
  Top Layer w12: v1(377.82,1461.61) 388.82,1450.61 388.82,1390.3 396.48,1382.64 U1.28@396.48,1348.5
  Inner Layer 1 w12: v1(377.82,1461.61) 377.82,1487.51 495,1604.7 495,1660 525,1690 525,1860
  other v1: 499,1874 525,1874 499,1904 525,1904 499,1934 525,1934
  other v2: 595,2010 625,2010 595,2050 625,2050 595,2085 625,2085 594,2120 625,2120 594,2155 625,2155
HDRV1_P: RH1.1 U1.27 | length 119.9
  Top Layer w12: RH1.1@417.82,1466.61 417.82,1465.67 417.82,1400.61 422.07,1396.36 U1.27@422.07,1348.5
HDRV2_N: C10.2 L1.2 QH2.1 QH2.2 QH2.3 QL2.5 QL2.6 QL2.7 QL2.8 QL2.9 U1.18 | length 588.1
  Top Layer w12: U1.18@652.38,1348.5 652.38,1384.87 665.82,1398.3 C10.2@665.82,1431.3 ; C10.2@672.82,1438.3 675,1440.48 v1(675,1471)
  Inner Layer 1 w12: v1(675,1471) 674,1471 653.78,1491.22 653.78,1515 685,1546.22 685,1697.76 660,1722.76 660,1830 695,1865 v1(720,1865)
  other v1: 746,1865 720,1895 746,1895 720,1925 746,1925
  other v2: 765,2010 815,2010 675,2050 720,2050 765,2050 815,2050 675,2085 720,2085 765,2085 815,2085 675,2120 720,2120 765,2120 815,2120 675,2155 720,2155 765,2155 815,2155
HDRV2_P: RH2.2 U1.19 | length 129.4
  Top Layer w12: U1.19@626.79,1348.5 626.79,1396.28 637.82,1407.3 637.82,1465.67 RH2.2@637.82,1473.3
LDRV1: RL1.1 U1.25 | length 124.7
  Top Layer w12: U1.25@473.25,1348.5 473.25,1465.67 RL1.1@473.25,1473.17
LDRV2: RL2.2 U1.21 | length 127.2
  Top Layer w12: U1.21@575.61,1348.5 575.61,1389.09 582.82,1396.3 582.82,1465.67 RL2.2@582.82,1472.74
MODE: R9.1 U1.4 | length 133.4
  Top Layer w10: v1@473.25,1056.75 U1.4@473.25,1124.09
  Bottom Layer w10: R9.1@428,1101 428.52,1101 429.6,1099.92 474.52,1055 v1(475,1055)
NetC8_2: C8.2 R5.1 | length 25.6
  Bottom Layer w10: R5.1@640,1074.25 C8.2@640,1099.88
NetC12_1: C12.1 R13.2 U1.13 | length 132.7
  Top Layer w10: U1.13@703.56,1124.09 703.56,1051.75 C12.1@725,1030.31 R13.2@755,1030.31
NetC12_2: C12.2 R15.2 U1.14 | length 80.3
  Top Layer w10: C12.2@725,1069.68 R15.2@755,1069.68 ; C12.2@729.15,1073.84 U1.14@729.15,1124.09
NetC16_2: C16.2 U2.4 | length 24.5
  Bottom Layer w12: C16.2@489.69,890 U2.4@489.69,914.53
NetD1_1: D1.1 R2.2 | length 38.7
  Bottom Layer w15: D1.1@346.34,1289.69 R2.2@385,1289.69
NetQH1_4: QH1.4 RH1.2 | length 365
  Inner Layer 1 w12: v1(425,1505) 515,1595 515,1655.96 542,1682.96 542,1803 v2(546,1807)
  Bottom Layer w12: QH1.4@533.92,1805 535.92,1807 v2(546,1807)
NetQH2_4: QH2.4 RH2.1 | length 547.6
  Top Layer w12: RH2.1@640,1505.04 v1(675,1505)
  Inner Layer 1 w12: v1(675,1505) 705,1535 705,1704.04 677,1732.04 677,1820.07 696.93,1840 v2(807.4,1840)
  Bottom Layer w12: v2(807.4,1840) 808.39,1839.02 QH2.4@808.39,1805.53
NetQL1_4: QL1.4 RL1.2 | length 429.1
  Inner Layer 1 w12: v1(490,1505) 515,1505 570,1560 570,1720 590,1740 v2(590,1853)
  Bottom Layer w12: 590,1839 v2(590,1853) QL1.4@590,1864
NetQL2_4: QL2.4 RL2.1 | length 504.1
  Inner Layer 1 w12: v1(565,1505) 600,1540 600,1695 630,1725 v2(630,1950)
  Bottom Layer w12: v2(630,1950) 642.13,1950 648.74,1943.39 QL2.4@659.47,1943.39
NetR6_1: R6.1 R7.1 | length 48.8
  Top Layer w10: R6.1@670,1000.32 697.13,1000.32 R7.1@712.44,985
NetR10_2: R10.2 U3.6 | length 40.4
  Top Layer w10: U3.6@589.29,1000.59 R10.2@629.72,1000.59
PGOOD: U1.17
